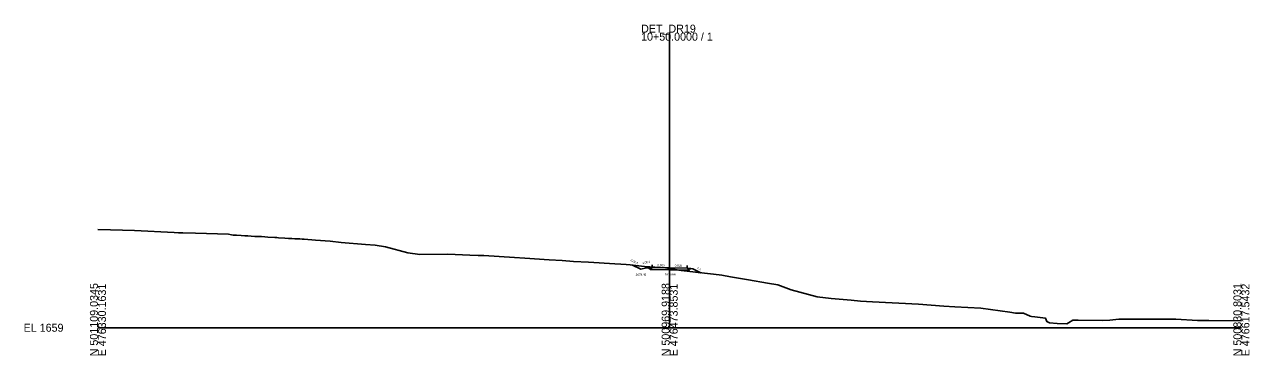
# Model space of a CAD drawing. Extents: x -26 to 403, y -10 to 3059.
# Drawn here: x -25.7 to 402.8, y 490.3 to 605.9 of the extents above; entities that cross this region are included whole.
import ezdxf

# ---------------------------------------------------------------- set-up
doc = ezdxf.new("R2010")
doc.units = 0
for name, color, linetype in [('Exist Cross Section Cell', 7, 'Continuous'), ('Exist XS Center Line Elevation Label', 7, 'Continuous'), ('Exist XS Ground Line', 7, 'Continuous'), ('Prop XS Ditch Slope Text', 7, 'Continuous'), ('Prop XS Ditch Standard Text', 7, 'Continuous'), ('Prop XS Dump Level', 7, 'Continuous'), ('Prop XS Earthwork Shape', 7, 'Continuous'), ('Prop XS EOT Tick Mark', 7, 'Continuous'), ('Prop XS Finish Grade', 7, 'Continuous'), ('Prop XS Finish Grade Earthwork', 7, 'Continuous'), ('Prop XS Finish Grade Pavement', 7, 'Continuous'), ('Prop XS Hydro Typical Ditch Data', 7, 'Continuous'), ('Prop XS Pvmt Edge Slope', 7, 'Continuous'), ('Prop XS SE Text', 7, 'Continuous'), ('Prop XS Shoulder Borrow Shape', 7, 'Continuous'), ('Prop XS Side Slope Text', 7, 'Continuous'), ('Prop XS Subgrade Earthwork', 7, 'Continuous')]:
    doc.layers.add(name, color=color, linetype=linetype)

msp = doc.modelspace()

# ---------------------------------------------------------------- linework, layer by layer
at = {"layer": 'Exist Cross Section Cell'}
for p, q in [((200, 500), (200, 603.1)), ((0, 500), (200, 500)), ((200, 500), (400, 500))]:
    msp.add_line(p, q, dxfattribs=at)
at = {"layer": 'Exist XS Ground Line'}
msp.add_lwpolyline([(0, 534.37), (4.42, 534.26), (12.75, 533.93), (26.67, 533.26), (28.22, 533.18), (29.67, 533.11), (34.12, 533.02), (45.71, 532.65), (46.67, 532.48), (47.29, 532.37), (48.13, 532.35), (48.45, 532.33), (50.08, 532.22), (51.34, 532.14), (52.38, 532.07), (53.6, 531.97), (54.84, 531.92), (55.33, 531.91), (55.91, 531.88), (57.22, 531.82), (58.41, 531.74), (59.42, 531.68), (61.87, 531.53), (62.53, 531.48), (63.21, 531.44), (65.36, 531.31), (66.63, 531.23), (67.81, 531.15), (68.86, 531.1), (69.51, 531.06), (70.62, 531.01), (71.46, 530.96), (72.19, 530.92), (76.14, 530.64), (81.26, 530.22), (85.12, 529.75), (93.59, 529.1), (96.96, 528.8), (100.58, 528.28), (108.39, 526.21), (112.59, 525.64), (122.35, 525.73), (130.14, 525.33), (133.05, 525.26), (134.94, 525.24), (145.69, 524.57), (149.32, 524.34), (157.88, 523.72), (162.43, 523.46), (166.35, 523.16), (171.55, 522.92), (180.83, 522.29), (182.9, 522.2), (184.83, 522.04), (186.21, 521.96), (191.23, 521.43), (198.51, 520.88), (200, 520.66), (204.08, 520.04), (208.12, 519.54), (215.29, 518.75), (218.21, 518.4), (221.23, 517.8), (227.61, 516.7), (234.19, 515.62), (237.81, 515.03), (242.48, 513.26), (251.64, 510.76), (256.44, 510.16), (263.46, 509.61), (266.75, 509.25), (270.98, 509.07), (287.02, 508.25), (295.86, 507.57), (299.79, 507.3), (308.86, 506.88), (318.99, 505.43), (320.93, 505.14), (323.8, 505.06), (326.14, 504.08), (326.57, 503.96), (327.79, 503.76), (331.48, 503.3), (332, 502.16), (332.9, 501.66), (335.59, 501.46), (338.91, 501.32), (339.51, 501.74), (341.05, 502.59), (342.95, 502.63), (351.44, 502.56), (353.99, 502.69), (357.09, 502.97), (357.93, 503), (377.03, 502.95), (384.69, 502.57), (386.39, 502.57), (388.61, 502.49), (400, 502.46)], dxfattribs=at)
at = {"layer": 'Prop XS Dump Level'}
for p, q in [((193.92, 521.03), (200, 520.91)), ((200, 520.91), (206.08, 520.78))]:
    msp.add_line(p, q, dxfattribs=at)
at = {"layer": 'Prop XS Earthwork Shape'}
for points in [[(193.26, 520.37), (192.65, 520.98), (191.89, 520.95), (189.87, 520.45), (186.99, 521.87), (191.23, 521.43), (198.51, 520.88), (200, 520.66), (203.2, 520.17), (200, 520.24), (193.92, 520.36)], [(206.08, 520.12), (203.2, 520.17), (204.08, 520.04), (208.12, 519.54), (210.9, 519.23), (208.11, 520.62), (207.36, 520.68), (206.77, 520.1)]]:
    msp.add_lwpolyline(points, close=True, dxfattribs=at)
at = {"layer": 'Prop XS EOT Tick Mark'}
for p, q in [((193.92, 521.03), (193.92, 522.03)), ((206.08, 520.78), (206.08, 521.78))]:
    msp.add_line(p, q, dxfattribs=at)
at = {"layer": 'Prop XS Finish Grade'}
for p, q in [((193.92, 521.03), (192.65, 520.98)), ((206.08, 520.78), (207.36, 520.68))]:
    msp.add_line(p, q, dxfattribs=at)
at = {"layer": 'Prop XS Finish Grade Earthwork'}
for p, q in [((189.87, 520.45), (186.99, 521.87)), ((191.89, 520.95), (189.87, 520.45)), ((192.65, 520.98), (191.89, 520.95)), ((207.36, 520.68), (208.11, 520.62)), ((208.11, 520.62), (210.9, 519.23))]:
    msp.add_line(p, q, dxfattribs=at)
at = {"layer": 'Prop XS Finish Grade Pavement'}
for p, q in [((193.92, 521.03), (200, 520.91)), ((200, 520.91), (206.08, 520.78))]:
    msp.add_line(p, q, dxfattribs=at)
at = {"layer": 'Prop XS Hydro Typical Ditch Data'}
for p, q in [((189.87, 520.45), (186.99, 521.87)), ((191.89, 520.95), (189.87, 520.45))]:
    msp.add_line(p, q, dxfattribs=at)
at = {"layer": 'Prop XS Pvmt Edge Slope'}
for p, q in [((193.92, 521.03), (193.26, 520.37)), ((206.08, 520.78), (206.77, 520.1))]:
    msp.add_line(p, q, dxfattribs=at)
at = {"layer": 'Prop XS Shoulder Borrow Shape'}
for points in [[(193.92, 521.03), (192.65, 520.98), (193.26, 520.37)], [(206.08, 520.78), (207.36, 520.68), (206.77, 520.1)]]:
    msp.add_lwpolyline(points, close=True, dxfattribs=at)
at = {"layer": 'Prop XS Subgrade Earthwork'}
for p, q in [((193.26, 520.37), (192.65, 520.98)), ((193.92, 520.36), (193.26, 520.37)), ((200, 520.24), (193.92, 520.36)), ((206.08, 520.12), (200, 520.24)), ((206.08, 520.12), (206.77, 520.1)), ((206.77, 520.1), (207.36, 520.68))]:
    msp.add_line(p, q, dxfattribs=at)

# ---------------------------------------------------------------- texts
at = {"layer": 'Exist Cross Section Cell'}
for s, p in [('DET_DR19', (190, 603.1)), ('10+50.0000 / 1', (190, 600.3)), ('EL 1659', (-26, 498.6))]:
    msp.add_text(s, height=2.8, dxfattribs=at).set_placement(p)
for s, p in [('N 501109.0345', (0, 490)), ('E 476330.1631', (2.8, 490)), ('N 500969.9188', (200, 490)), ('E 476473.8531', (202.8, 490)), ('N 500830.8031', (400, 490)), ('E 476617.5432', (402.8, 490))]:
    msp.add_text(s, height=2.8, rotation=90, dxfattribs=at).set_placement(p)
at = {"layer": 'Exist XS Center Line Elevation Label'}
msp.add_text('1679.66', height=0.75, dxfattribs=at).set_placement((198.31, 518.28))
at = {"layer": 'Prop XS Ditch Slope Text'}
msp.add_text('4.05:1', height=0.75, rotation=13.8828, dxfattribs=at).set_placement((190.52, 522.15))
at = {"layer": 'Prop XS Ditch Standard Text'}
msp.add_text('1679.45', height=0.75, dxfattribs=at).set_placement((188.07, 518.2))
at = {"layer": 'Prop XS Dump Level'}
for p in [(191.89, 520.91), (208.11, 520.58)]:
    msp.add_text('Case1', height=0.04, dxfattribs=at).set_placement(p)
at = {"layer": 'Prop XS SE Text'}
for p in [(195.68, 521.49), (201.76, 521.37)]:
    msp.add_text('0.020', height=0.75, rotation=358.8542, dxfattribs=at).set_placement(p)
at = {"layer": 'Prop XS Side Slope Text'}
for s, rotation, p in [('2.02:1', 333.6963, (186.17, 523.41)), ('2:1', 333.4349, (209.49, 520.65))]:
    msp.add_text(s, height=0.75, rotation=rotation, dxfattribs=at).set_placement(p)

doc.saveas('drawing.dxf')
